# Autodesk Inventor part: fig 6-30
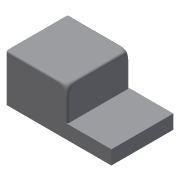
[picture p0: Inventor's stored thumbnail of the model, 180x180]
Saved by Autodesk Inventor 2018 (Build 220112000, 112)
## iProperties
Created: 2004-05
Part Number: fig 6-30
Document SubType Name: Modeling
Designer: CADCIM Technologies
Manufacturer: Standard
Standards Organization: Custom
Density: 1 g/cm^3
Material: Generic
Appearance: Default
Author: CADCIM Technologies
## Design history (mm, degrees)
node "Sketch1"
sketch "Sketch2"
  geometry: L1 (0.098, 47.711)-(0.098, 0.049); L2 (0.098, 0.049)-(-105.483, 0.049); L3 (-105.483, 0.049)-(-105.483, 14.192); L4 (-105.483, 14.192)-(-61.139, 14.192); L5 (-61.139, 14.192)-(-61.139, 47.711); L6 (-61.139, 47.711)-(0.098, 47.711)
  constraints: 12 end point, 3 parallel, 2 perpendicular, 1 vertical
extrude "Extrusion1" new body sketch "Sketch2" stored distance "d0" = 62.5; taper "d1" = 0 deg
fillet "Fillet6" dims "d43" = 10, "d44" = 10, "d45" = 10, "d46" = 10, "d47" = 10, "d48" = 10, "d49" = 2
body "Solid1"
